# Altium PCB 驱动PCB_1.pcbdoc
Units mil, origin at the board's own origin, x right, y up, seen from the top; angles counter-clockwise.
Board outline 1915 x 3750 mil, 2 copper layers (Top Layer, Bottom Layer); 35 components, 43 nets, 159 pads, 130 vias.
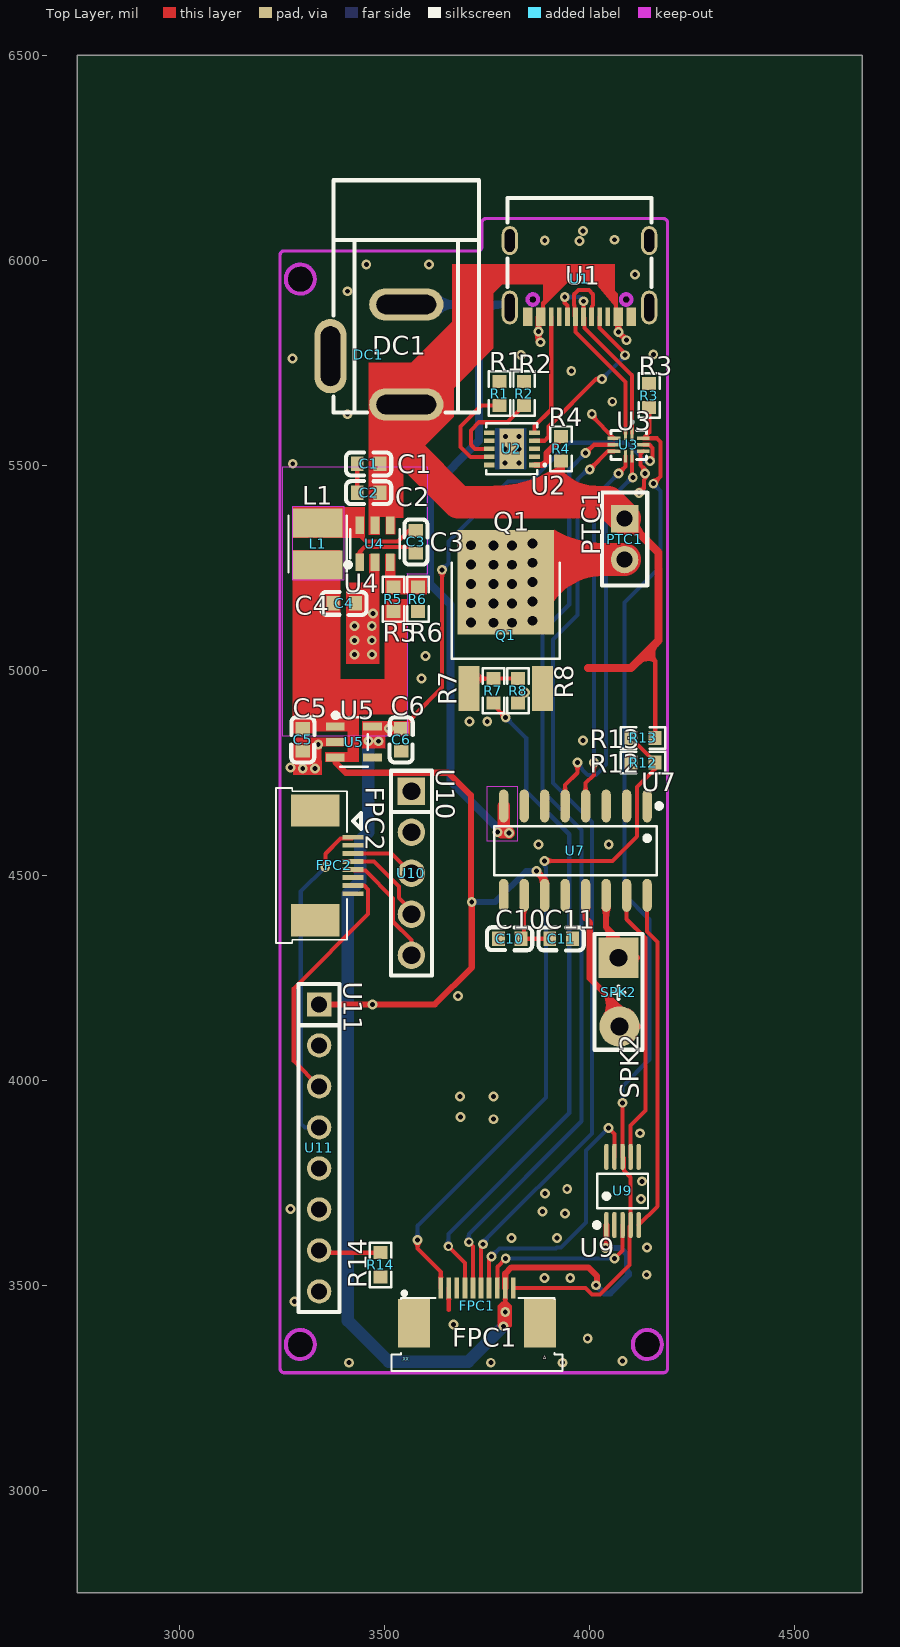
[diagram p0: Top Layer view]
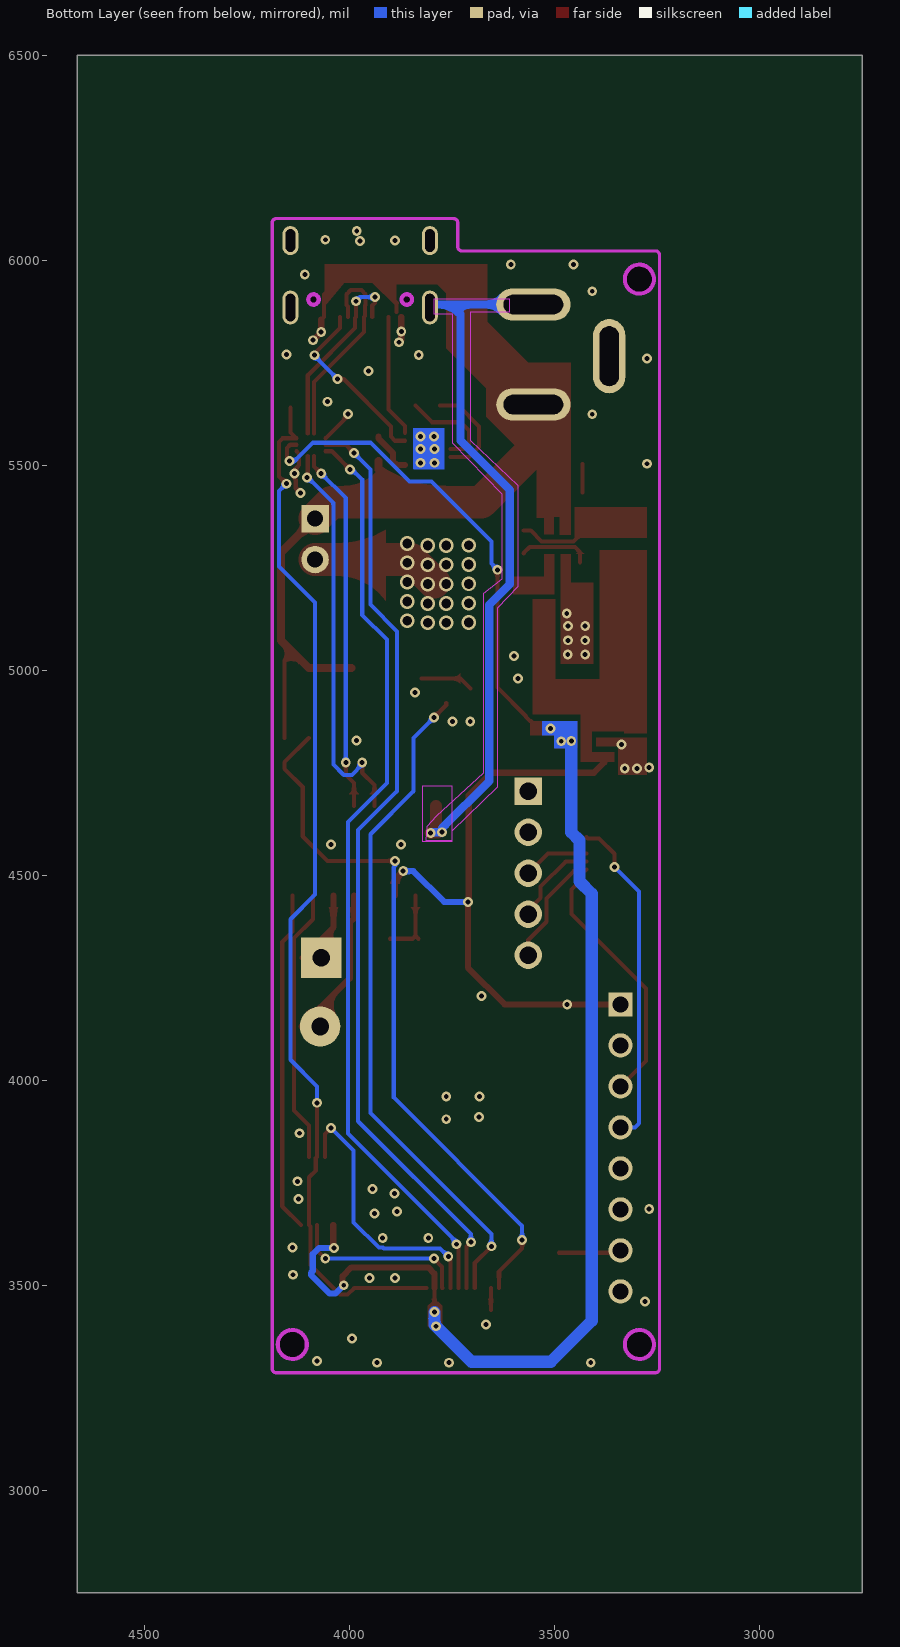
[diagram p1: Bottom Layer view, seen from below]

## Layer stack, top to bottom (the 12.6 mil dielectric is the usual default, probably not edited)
Top Layer: signal copper (thickness not stored)
Dielectric: dielectric 12.6, FR-4, Dk 4.8
Bottom Layer: signal copper (thickness not stored)

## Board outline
4665,2750 2750,2750 2750,6500 4665,6500
cut-out: 3329.43,5953.89 ccw(c3294,5953.67) 3258.57,5953.89 ccw(c3294,5954.11)
cut-out: 3329.43,3355.47 ccw(c3294,3355.25) 3258.57,3355.47 ccw(c3294,3355.69)
cut-out: 4175.89,3355.47 ccw(c4140.45,3355.47) 4105.02,3355.47 ccw(c4140.45,3355.47)

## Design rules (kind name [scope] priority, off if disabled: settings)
BoardOutlineClearance copperThickness1oz [All] p0: genericclearance=10 ignorepadtopadclearanceinfootprint=FALSE except(0: Arc-SplitContinuation Track-SplitContinuation SMDPad-SplitContinuation THPad-SplitContinuation Via-SplitContinuation Fill-SplitContinuation Poly-SplitContinuation Region-SplitContinuation Text-SplitContinuation; 6: Track-CutoutEdge SMDPad-CutoutEdge THPad-CutoutEdge Via-CutoutEdge Region-CutoutEdge; 11.8: Track-OutlineEdge SMDPad-OutlineEdge THPad-OutlineEdge Via-OutlineEdge Fill-OutlineEdge Region-OutlineEdge Poly-OutlineEdge Text-OutlineEdge Fill-CutoutEdge)
BoardOutlineClearance copperThickness2oz [All] p0: genericclearance=10 ignorepadtopadclearanceinfootprint=FALSE except(0: Arc-SplitContinuation Track-SplitContinuation SMDPad-SplitContinuation THPad-SplitContinuation Via-SplitContinuation Fill-SplitContinuation Poly-SplitContinuation Region-SplitContinuation Text-SplitContinuation; 6: Track-CutoutEdge SMDPad-CutoutEdge THPad-CutoutEdge Via-CutoutEdge Region-CutoutEdge; 11.8: Track-OutlineEdge SMDPad-OutlineEdge THPad-OutlineEdge Via-OutlineEdge Fill-OutlineEdge Region-OutlineEdge Poly-OutlineEdge Text-OutlineEdge Fill-CutoutEdge)
Clearance copperThickness1oz [(InNet('GND') OR InNet('3V3') OR InNet('ADC_VIN') OR InNet('$2N1457') OR InNet('$2N1458') OR InNet('VIN') OR InNet('5V') OR InNet('$2N1719') OR InNet('ESP_TX') OR InNet('ESP_RX') OR InNet('DN1') OR InNet('DP1') OR InNet('$2N173') OR InNet('$2N169') OR InNet('$2N860') OR InNet('$2N846') OR InNet('$2N1461') OR InNet('$2N861') OR InNet('DAC') OR InNet('SPK2') OR InNet('SPK1') OR InNet('SCK') OR InNet('DOUT') OR InNet('CC1') OR InNet('DN') OR InNet('DP') OR InNet('CC2') OR InNet('USBDM') OR InNet('USBDP') OR InNet('CH7800_RX') OR InNet('CH7800_TX') OR InNet('SW') OR InNet('PTC') OR InNet('$2N3080') OR InNet('GPIO17') OR InNet('GPIO16') OR InNet('GPIO15') OR InNet('SCL') OR InNet('SDA') OR InNet('AD0') OR InNet('XDA') OR InNet('XCL') OR InNet('INT'))] p1: gap=7 ignorepadtopadclearanceinfootprint=FALSE except(4: Track-Track; 6: Track-SMDPad SMDPad-SMDPad Track-THPad SMDPad-THPad THPad-THPad Track-Via SMDPad-Via THPad-Via Via-Via SMDPad-Fill THPad-Fill Via-Fill Fill-Fill Track-Region SMDPad-Region THPad-Region Via-Region Region-Region Track-Poly SMDPad-Poly THPad-Poly Via-Poly Fill-Poly Region-Poly Poly-Poly Track-Text SMDPad-Text THPad-Text Via-Text Fill-Text Region-Text Poly-Text Text-Text; 6.9: Track-Hole SMDPad-Hole THPad-Hole Via-Hole Fill-Hole Region-Hole Poly-Hole Text-Hole Sheet-Hole; 11.8: Track-Fill Fill-Region Track-Sheet SMDPad-Sheet THPad-Sheet Via-Sheet Fill-Sheet Region-Sheet Poly-Sheet Text-Sheet)
Clearance copperThickness2oz [All] p1: gap=7 ignorepadtopadclearanceinfootprint=FALSE except(6: Track-SMDPad SMDPad-SMDPad Track-THPad SMDPad-THPad THPad-THPad Track-Via SMDPad-Via THPad-Via Via-Via SMDPad-Fill THPad-Fill Via-Fill Fill-Fill Track-Region SMDPad-Region THPad-Region Via-Region Region-Region Track-Poly SMDPad-Poly THPad-Poly Via-Poly Fill-Poly Region-Poly Poly-Poly Track-Text SMDPad-Text THPad-Text Via-Text Fill-Text Region-Text Poly-Text Text-Text; 6.9: Track-Hole SMDPad-Hole THPad-Hole Via-Hole Fill-Hole Region-Hole Poly-Hole Text-Hole Sheet-Hole; 8: Track-Track; 11.8: Track-Fill Fill-Region Track-Sheet SMDPad-Sheet THPad-Sheet Via-Sheet Fill-Sheet Region-Sheet Poly-Sheet Text-Sheet)
DiffPairsRouting differentialPair [All] p1: maxuncoupledlength=10 minlimit=6 maxlimit=6 mostfreqgap=6 toplayer_minwidth=5 toplayer_prefwidth=10 toplayer_maxwidth=100 bottomlayer_minwidth=5 bottomlayer_prefwidth=10 bottomlayer_maxwidth=100
PasteMaskExpansion pasteMaskExpansion [All] p1: expansion=0
PlaneConnect innerPlane [All] p1: planeconnectstyle=Relief reliefexpansion=20 reliefentries=4 reliefconductorwidth=10 reliefairgap=10
PolygonConnect copperRegion [All] p1: connectstyle=Relief reliefentries=4 reliefconductorwidth=10 polygonreliefangle="90 Angle" airgapwidth=10
RoutingVias viaSize [All] p1: viastyle="Through Hole" holewidth=12.0078 minholewidth=11.811 maxholewidth=248.0314 width=24.0158 minwidth=19.685 maxwidth=393.7008
SolderMaskExpansion solderMaskExpansion [All] p1: useseparateexpansions=TRUE expansion=2 expansionbottom=2
Width copperThickness1oz [All] p1: maxlimit=100 minlimit=5 preferedwidth=10
Width copperThickness2oz [All] p1: maxlimit=100 minlimit=8 preferedwidth=10

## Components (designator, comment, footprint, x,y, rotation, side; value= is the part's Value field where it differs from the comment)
C1 "CGA0603X7R104K500JT" C0603 3460.47,5503.23 r180 top
C2 "CL10A106KP8NNNC" C0603 3460.47,5433.23 r180 top
C3 "CGA0603X7R104K500JT" C0603 3576.08,5313.01 r90 top
C4 "CGA0603X7R104K500JT" C0603 3401.08,5163.01 r0 top
C5 "CGA0603X7R104K500JT" C0603 3300,4830 r270 top
C6 "CL10A106KP8NNNC" C0603 3540,4830 r270 top
C10 "CL10A105KA8NNNC" C0603 3805,4345 r0 top
C11 "CL10A105KA8NNNC" C0603 3930,4345 r180 top
DC1 "DC005" DC-IN-TH_DC005 3460,5770 r270 top locked
FPC1 "F0501-T-10-20T-R" FPC-SMD_F0501-T-10-20T-R 3725,3450 r0 top
FPC2 "F0501-T-08-20T-R" FPC-SMD_8P-P0.50_L4.4-W9.6 3376.34,4523.81 r270 top
L1 "CD32-4R7M 4.7UH" IND-SMD_L3.5-W3.0 3336.08,5308.01 r90 top
PTC1 "HDR-F_2.54_1x2P" HDR-TH_2P-P2.54-V-F 4085,5320 r270 top
Q1 "AOD4184L" TO-252-2_L6.6-W6.1-P4.57-LS9.9-TL-CW 3795,5085 r90 top
R1 "0603WAF1002T5E" R0603 3780,5675 r90 top
R2 "0603WAF1002T5E" R0603 3840,5675 r90 top
R3 "0603WAF1002T5E" R0603 4145,5670 r270 top
R4 "0603WAF100JT5E" R0603 3930,5540 r270 top
R5 "FRC0603F2703TS" R0603 3521.08,5173.01 r270 top
R6 "0603WAF5102T5E" R0603 3581.08,5173.01 r90 top
R7 "0603WAF1000T5E" R0603 3765,4950 r90 top
R8 "0603WAF1002T5E" R0603 3825,4950 r270 top
R12 "0603WAF5102T5E" R0603 4130,4775 r180 top
R13 "0603WAF2703T5E" R0603 4130,4835 r180 top
R14 "Res_0603" R0603 3489.66,3549.66 r90 top
SPK2 "GSPK3013P-8R0.15W" SPK-TH_BD30.0-P15.00-D0.8-L-RD 4070,4215 r270 top
U1 "TYPE-C16PIN" USB-C-SMD_TYPE-C16PIN 3975,5955 r180 top
U2 "HUSB238_002DD" DFN-10_L3.0-W3.0-P0.50-BL-EP2.5 3810,5540 r90 top
U3 "BL1532TQFN" QFN-10_L1.4-W1.8-P0.40-BL 4095,5550 r180 top
U4 "RY8411_C2935411" SOT-23-6_L2.9-W1.6-P0.95-LS2.8-TL 3476.14,5308.63 r90 top
U5 "ME6212C33M5G" SOT-23-5_L3.0-W1.7-P0.95-LS2.8-BL 3425,4825 r270 top
U7 "CH7800" SOP-16_L9.9-W3.9-P1.27-LS6.0-BL 3965,4560 r180 top
U9 "BL1555MM" MSOP-10_L3.0-W3.0-P0.50-LS5.0-BL 4080,3730 r0 top
U10 "HB-PH3-25415PB2GOP" HDR-TH_5P-P2.54-V-M 3565,4505 r270 top
U11 "HB-PH3-25418PB2GOP" HDR-TH_8P-P2.54-V-M 3340,3835 r270 top

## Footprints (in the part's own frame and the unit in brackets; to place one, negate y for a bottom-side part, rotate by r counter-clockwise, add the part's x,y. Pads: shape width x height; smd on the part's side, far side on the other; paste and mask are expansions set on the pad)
C0603 [mm]
  rect 0.8x0.9 smd: 1(-0.7,0) 2(0.7,0)
  silkscreen extent -1.41,-0.71 1.39,0.72
DC-IN-TH_DC005 [mm]
  oval 2x4.6 hole 1.2 slot 3.7 at 90 deg: 1(3.1,2.35) 2(-3.1,2.35)
  oval 4.6x2 hole 1.2 slot 3.7 at 0 deg: 3(0.1,-2.35)
  silkscreen extent -10.8,-2.15 3.6,6.85
DFN-10_L3.0-W3.0-P0.50-BL-EP2.5 [mm]
  rect 0.28x0.665 smd: 1(-1,-1.407) 2(-0.5,-1.407) 3(0,-1.407) 4(0.5,-1.407) 5(1,-1.407) 6(1,1.407) 7(0.5,1.407) 8(0,1.407) 9(-0.5,1.407) 10(-1,1.407)
  rect 2.5x1.5 smd: 11(0,0)
  silkscreen extent -1.58,-2.12 1.58,1.58
FPC-SMD_8P-P0.50_L4.4-W9.6 [mm]
  rect 2x3 smd: 0(-3.4,-1.175) 0(3.4,-1.175)
  rect 0.3x1.3 smd: 1(-1.75,1.175) 2(-1.25,1.175) 3(-0.75,1.175) 4(-0.25,1.175) 5(0.25,1.175) 6(0.75,1.175) 7(1.25,1.175) 8(1.75,1.175)
  silkscreen extent -4.8,-3.6 4.8,1.68
FPC-SMD_F0501-T-10-20T-R [mm]
  rect 0.3x1.3 smd: 1(-2.25,1.097) 2(-1.75,1.097) 3(-1.25,1.097) 4(-0.75,1.097) 5(-0.25,1.097) 6(0.25,1.097) 7(0.75,1.097) 8(1.25,1.097) 9(1.75,1.097) 10(2.25,1.097)
  rect 2x3 smd: 11(3.9,-1.097) 12(-3.9,-1.097)
  silkscreen extent -5.3,-4.03 5.3,0.87
HDR-TH_2P-P2.54-V-F [mm]
  rect 1.7x1.7 hole 1: 1(-1.27,0)
  round 1.7 hole 1: 2(1.27,0)
  silkscreen extent -2.88,-1.39 2.88,1.4
HDR-TH_5P-P2.54-V-M [mm]
  rect 1.7x1.7 hole 1.1: 1(-5.08,0)
  round 1.7 hole 1.1: 2(-2.54,0) 3(0,0) 4(2.54,0) 5(5.08,0)
  silkscreen extent -6.35,-1.27 6.35,1.27
HDR-TH_8P-P2.54-V-M [mm]
  rect 1.5x1.5 hole 1: 1(-8.89,0)
  round 1.5 hole 1: 2(-6.35,0) 3(-3.81,0) 4(-1.27,0) 5(1.27,0) 6(3.81,0) 7(6.35,0) 8(8.89,0)
  silkscreen extent -10.16,-1.27 10.16,1.27
IND-SMD_L3.5-W3.0 [mm]
  rect 1.8x3.12 smd: 1(1.303,0) 2(-1.303,0)
  silkscreen extent -1.75,-1.8 1.75,1.8
MSOP-10_L3.0-W3.0-P0.50-LS5.0-BL [mm]
  oval 0.28x1.62 smd: 1(-1,-2.11) 2(-0.5,-2.11) 3(0,-2.11) 4(0.5,-2.11) 5(1,-2.11) 6(1,2.11) 7(0.5,2.11) 8(0,2.11) 9(-0.5,2.11) 10(-1,2.11)
  silkscreen extent -1.74,-2.26 1.58,1.07
QFN-10_L1.4-W1.8-P0.40-BL [mm]
  rect 0.2x0.9 smd: 1(-0.2,-0.65)
  rect 0.2x0.8 smd: 2(0.2,-0.7) 6(0.2,0.7) 7(-0.2,0.7)
  rect 0.8x0.2 smd: 3(0.9,-0.4) 4(0.9,0) 5(0.9,0.4) 8(-0.9,0.4) 9(-0.9,0) 10(-0.9,-0.4)
  silkscreen extent -1.1,-1.48 1.09,0.91
R0603 [mil]
  rect 31.75x34.02 smd: 1(-29.66,0) 2(29.66,0)
  silkscreen extent -55,-26 55,26
SOP-16_L9.9-W3.9-P1.27-LS6.0-BL [mil]
  oval 22.6x80.24 smd: 1(-175,-109.02) 2(-125,-109.02) 3(-75,-109.02) 4(-25,-109.02) 5(25,-109.02) 6(75,-109.02) 7(125,-109.02) 8(175,-109.02) 9(175,109.02) 10(125,109.02) 11(75,109.02) 12(25,109.02) 13(-25,109.02) 14(-75,109.02) 15(-125,109.02) 16(-175,109.02)
  silkscreen extent -210,-115 198,60
SOT-23-5_L3.0-W1.7-P0.95-LS2.8-BL [mm]
  rect 0.49x1.157 smd: 1(-0.95,-1.154) 2(0,-1.154) 3(0.95,-1.154)
  rect 0.49x1.175 smd: 4(0.95,1.154) 5(-0.95,1.154)
  silkscreen extent -1.8,-1.29 1.53,0.85
SOT-23-6_L2.9-W1.6-P0.95-LS2.8-TL [mil]
  rect 42.2x20.95 smd: 1(-45.24,37.4) 2(-45.24,0) 3(-45.24,-37.4) 4(45.24,-37.4) 5(45.24,0) 6(45.24,37.4)
  silkscreen extent -57,-61 35,72
SPK-TH_BD30.0-P15.00-D0.8-L-RD [mm]
  rect 2.5x2.5 hole 1.1: 1(-2.128,0)
  round 2.5 hole 1.1: 2(2.128,0.064)
  silkscreen extent -3.59,-1.47 3.57,1.5
TO-252-2_L6.6-W6.1-P4.57-LS9.9-TL-CW [mm]
  rect 2.8x1.3 smd: 1(-3.292,2.273) 3(-3.292,-2.273)
  rect 6.5x6 smd: 2(3.292,0)
  silkscreen extent -1.46,-3.35 4.51,3.34
USB-C-SMD_TYPE-C16PIN [mm]
  oval 1x2.1 hole 0.6 slot 1.7 at 90 deg: 1(-4.32,1.787) 2(4.32,1.787)
  oval 1x1.8 hole 0.6 slot 1.4 at 90 deg: 3(-4.32,-2.362) 4(4.32,-2.362)
  rect 0.6x1.15 smd: A1B12(-3.2,2.362) A4B9(-2.4,2.362) B1A12(3.2,2.362) B4A9(2.4,2.362)
  rect 0.3x1.15 smd: A5(-1.25,2.362) A6(-0.25,2.362) A7(0.25,2.362) A8(1.25,2.362) B5(1.75,2.362) B6(0.75,2.362) B7(-0.75,2.362) B8(-1.75,2.362)
  Board Outline Layer circle w0.005: c2.89,1.288 r0.325
  Board Outline Layer circle w0.005: c-2.89,1.288 r0.325
  Board Outline Layer circle w0.254: c2.89,1.288 r0.325
  Board Outline Layer circle w0.254: c-2.89,1.288 r0.325
  Multi-Layer board cut-out: 2.565,1.288 2.611,1.128 2.729,1.012 2.89,0.969 3.051,1.012 3.169,1.128 3.215,1.288 3.215,1.288 3.169,1.448 3.051,1.564 2.89,1.607 2.729,1.564 2.611,1.448 2.565,1.288
  Multi-Layer board cut-out: -3.215,1.288 -3.183,1.147 -3.093,1.034 -2.962,0.971 -2.818,0.971 -2.687,1.034 -2.597,1.147 -2.565,1.288 -2.565,1.288 -2.597,1.429 -2.687,1.542 -2.818,1.605 -2.962,1.605 -3.093,1.542 -3.183,1.429 -3.215,1.288
  silkscreen extent -4.45,-5 4.45,0.52

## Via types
v1: diameter 24.02, hole 12.01, Top Layer to Bottom Layer, 110 vias
v2: diameter 36, hole 24, Top Layer to Bottom Layer, 20 vias

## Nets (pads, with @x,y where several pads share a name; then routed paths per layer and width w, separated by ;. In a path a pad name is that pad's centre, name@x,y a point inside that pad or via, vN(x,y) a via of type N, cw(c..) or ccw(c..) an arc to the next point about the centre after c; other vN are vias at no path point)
3V3: C6.1 FPC1.9 U3.9 U5.5 U9.1 | length 3735.6
  Top Layer w10: C6.1 3558.64,4876.2 3560.45,4876.2 3570.3,4886.05 3570.3,4887.86 3640,4957.56 v1(3640,5245) ; v1(3793.89,3434.35) FPC1.9 ; U3.9 4145.49,5550 4153.22,5542.27 4153.22,5516.21 v1(4147.01,5510)
  Top Layer w15: FPC1.9 3793.89,3528.48 3808.89,3543.48 3996.52,3543.48 4017.91,3522.09 4017.91,3502.91 v1(4015,3500) ; v1(4038.76,3591.24) 4040.63,3593.11 U9.1
  Bottom Layer w10: v1(3640,5245) 3655,5260 3655,5314.4 3800.6,5460 3855,5460 3950,5555 4090,5555 4135,5510 v1(4147.01,5510)
  Bottom Layer w15: v1(4015,3500) 4035,3480 4050,3480 4095,3525 4095,3530 4090.49,3534.51 4090.49,3575.9 4075.56,3590.83 4039.17,3590.83 v1(4038.76,3591.24)
  Bottom Layer w30: v1(3460,4827.56) 3460,4605 3440,4585 3440,4485 3410,4455 3410,3413.39 3510,3313.39 3703.39,3313.39 v1(3790,3400) 3793.89,3403.89 v1(3793.89,3434.35)
  other v1: 3484.55,4826.86 3510.37,4858.32
5V: C4.1 C5.1 L1.2 R5.2 U5.1 U5.3 U7.11 U11.1 | length 1461.6
  Top Layer w15: U11.1 v1(3470,4185) 3622.16,4185 3712.14,4274.98 v1(3712.14,4435) ; U5.3 3379.58,4775.42 3405,4750 3655,4750 3710,4695 v1@3710,4435 ; v1(3870,4510) 3890,4490 U7.11
  Bottom Layer w15: v1(3712.14,4435) 3770,4435 3845,4510 v1(3870,4510)
$2N169: Q1.1 R7.2 R8.1 | length 129.5
  Top Layer w10: Q1.1 3729.78,4979.66 R7.2 R8.1
$2N173: PTC1.2 Q1.2 | length 312.9
  Top Layer w80: Q1.2 3850.39,5270 PTC1.2
  other v2: 3710,5116.42 3765,5115.71 3810,5115.71 3860,5120.71 3765,5162.85 3810,5162.85 3710,5163.56 3860,5167.85 3765,5210 3810,5210 3710,5210.71 3860,5215 3765,5257.15 3810,5257.15 3710,5257.85 3860,5262.15 3765,5304.29 3810,5304.29 3710,5305 3860,5309.29
$2N846: R4.1 U2.1 | length 107.6
  Top Layer w15: U2.1 3885.63,5500.63 3895,5510 3895,5530.22 3930,5565.22 R4.1
$2N860: R1.1 U2.9 | length 245.7
  Top Layer w10: U2.9 3709.68,5520.32 3685,5545 3685,5595 3735.34,5645.34 R1.1
$2N861: R2.1 U2.8 | length 238.7
  Top Layer w10: U2.8 3720,5540 3710,5550 3710,5585 3730,5605 3799.66,5605 R2.1
$2N1457: C3.2 L1.1 U4.6 | length 178.9
  Top Layer w10: U4.6 3444.36,5348.26 3444.36,5324.02 3454.2,5314.17 3532.39,5314.17 3558.79,5340.57 C3.2
$2N1458: C3.1 U4.1 | length 173
  Top Layer w10: U4.1 3438.74,5287.82 3451.08,5300.15 3561.38,5300.15 C3.1
$2N1461: R5.1 R6.2 U4.3
$2N1719: C10.2 C11.2 U7.10 | length 174.6
  Top Layer w10: C10.2 C10.2@3840,4352.44 ; U7.10 C10.2@3840,4352.44 ; C11.2 3847.44,4345 C10.2@3840,4352.44
$2N3080: FPC1.3
AD0: R14.2 U11.7 | length 152
  Top Layer w10: U11.7 3345.68,3579.32 R14.2
ADC_VIN: FPC1.1 R12.1 R13.2 | length 1729
  Top Layer w10: v1(3580,3610) 3580,3590 3636.41,3533.59 FPC1.1 ; v1(3890,4535) 4055,4535 4115,4595 4115,4715 4159.66,4759.66 R12.1 4159.66,4775.68 R13.2
  Bottom Layer w10: v1(3580,3610) 3580,3645 3892.99,3957.99 3892.99,4519.52 3890,4522.52 v1(3890,4535)
CC1: U1.A5 U2.4 | length 442.7
  Top Layer w10: U2.4 3890,5559.69 3900,5569.69 3900,5595 4015,5710 v1(4030,5710) ; U1.A5@4024.21,5861.88 4024.21,5834.56 4086.38,5772.39 v1(4086.38,5768.47)
  Bottom Layer w10: v1(4030,5710) 4086.38,5766.38 v1(4086.38,5768.47)
CC2: U1.B5 U2.5 | length 299.4
  Top Layer w10: U2.5 3865.41,5595.41 3906.1,5636.1 U1.B5@3906.1,5861.88
CH7800_RX: U7.16 U9.5 | length 833.3
  Top Layer w10: U9.5 4165,3692.56 4165,4337.56 4140,4362.56 U7.16
CH7800_TX: U7.15 U9.7 | length 672
  Top Layer w10: U7.15 4090,4392.73 4136.02,4346.71 4136.02,3926.02 4099.69,3889.69 U9.7
DAC: U7.9
DN: U1.A7 U1.B7 U3.2 | length 502.2
  Top Layer w10: U1.B7@4004.53,5861.88 4005,5862.35 4005,5887.48 4007.99,5890.48 4007.99,5917.01 3997.93,5927.07 3972.07,5927.07 3962.01,5917.01 3962.01,5890.48 3962.93,5889.56 3962.93,5864.11 3965.16,5861.88 3965.16,5824.84 4087.13,5702.87 U3.2
DN1: FPC1.5 U3.4 | length 2315.6
  Top Layer w10: v1(3705,3605) 3715.16,3594.84 FPC1.5 ; v1(3990,5530) 4010,5550 U3.4
  Bottom Layer w10: v1(3705,3605) 3705,3625 3980,3900 3980,4610 3885,4705 3885,5095 3950,5160 3950,5490 v1(3990,5530)
DOUT: U9.10
DP: U1.A6 U1.B6 U3.1 | length 472.3
  Top Layer w10: v1(3939.02,5910) 3939.02,5895.98 3945.47,5889.53 U1.B6@3945.47,5861.88 ; v1(3985,5900) 3985,5862.04 3984.84,5861.88 3987.64,5859.08 3987.64,5834.69 4102.87,5719.46 U3.1@4102.87,5577.56
  Bottom Layer w10: v1(3939.02,5910) 3975,5910 v1(3985,5900)
DP1: FPC1.6 U3.5 | length 2266.2
  Top Layer w10: FPC1.6 3734.84,3594.84 v1(3740,3600) ; v1(4000,5490) 4044.25,5534.25 U3.5
  Bottom Layer w10: v1(3740,3600) 3740,3605 4005,3870 4005,4630 3910,4725 3910,5075 3970,5135 3970,5465 3995,5490 v1(4000,5490)
ESP_RX: FPC1.7 U9.9 | length 673.8
  Top Layer w10: FPC1.7 3754.53,3564.53 v1(3760,3570) ; v1(4046.01,3883.5) 4060.32,3869.19 U9.9
  Bottom Layer w10: v1(3760,3570) 3780,3590 3917.48,3590 3919.49,3592.01 3929.52,3592.01 3990.77,3653.25 3990.77,3828.25 v1(4046.01,3883.5)
ESP_TX: FPC1.8 U9.3 | length 435.6
  Top Layer w10: FPC1.8 3775,3493.96 3775,3545 v1(3795,3565) ; v1(4060,3565) 4080,3585 U9.3
  Bottom Layer w10: v1(3795,3565) v1(4060,3565)
GND: C1.2 C2.2 C4.2 C5.2 C6.2 C10.1 C11.1 DC1.2 DC1.3 FPC1.2 FPC1.11 FPC1.12 FPC2.0 Q1.3 R1.2 R2.2 R3.1 R6.1 R8.2 R12.2 R14.1 U2.11 U3.3 U3.8 U4.2 U5.2 U7.8 U7.12 U9.6 U11.2 | length 2104.5
  Top Layer w10: C2.2 C1.2 ; 3656.11,3440 FPC1.2 ; v1(4005,5625) 4005,5620.32 U3.3@4059.57,5565.75 ; v1(4120.18,5432.75) 4132.01,5444.58 4132.01,5464.52 4135,5467.52 v1(4135,5480) 4135,5489.49 4124.02,5500.48 4124.02,5527.84 U3.8
  Top Layer w30: U7.8 3790,4610 3785,4605 3800.97,4605 v1(3802.99,4602.98)
  Bottom Layer w20: DC1.2 3753.47,5892.04 ; v1(3802.99,4602.98) 3800.97,4605 v1(3775,4605) 3775,4615 3660,4730 3660,5160 3610,5210 3610,5440 3730,5560 3730,5868.57 3753.47,5892.04 ; 3804.72,5882.75 3795.43,5892.04 3753.47,5892.04
  other v1: 3412.64,3311.09 3758.66,3311.09 3933.66,3311.09 4080,3315 3995,3370 3667.76,3403.86 3280,3460 3890,3517.99 3952.34,3517.99 4138.89,3525.68 4140,3592 3808.8,3615 3920,3615 3940,3675 3885,3680 3270,3686.12 4125,3710 3891.26,3723.74 3945,3735 4127.67,3753.54 4122.68,3870.65 3765,3905 3685,3910 3683.69,3960 3765,3960 3678.89,4205.68 3875,4575 4046.38,4575 3299.99,4760.61 3329.71,4760.61 3270,4762.71 3337.81,4818.97 3983.68,4828.29 3706.46,4875 3750,4875 3841.65,4945.79 3590,4980 3599.79,5034.75 3426.08,5038.01 3468.75,5038.01 3426.08,5073.01 3468.4,5073.01 3426.15,5107.65 3468.4,5107.65 3471.08,5138.01 3275.62,5503.64 3793.33,5506.01 3827.51,5506.01 3793.33,5540 3827.51,5540 3795,5570 3827.51,5570 3408.89,5624.44 4055,5655 3955,5730 3275,5760 3832.08,5769.09 4155,5770 3408.89,5924.44 4110,5965 3455,5990 3607.59,5990 3975,6047.11 3890.29,6048.12 4060,6050 3983.37,6071.38
GPIO15: FPC2.3 U10.3 | length 162.4
  Top Layer w10: FPC2.3 3516.66,4553.34 U10.3
GPIO16: FPC2.4 U10.4 | length 217.4
  Top Layer w10: FPC2.4 3473.48,4533.66 3535,4472.14 3535,4445 3565,4415 U10.4
GPIO17: FPC2.5 U10.5 | length 284
  Top Layer w10: FPC2.5 3425.4,4511.18 3452.75,4511.18 3520.55,4443.37 3520.55,4386.59 3565,4342.14 U10.5
INT: U11.8
PTC: FPC1.4 R7.1 | length 1642.7
  Top Layer w10: v1(3655,3595) 3695.47,3554.53 FPC1.4 ; R7.1 3765,4915 v1(3795,4885)
  Bottom Layer w10: v1(3655,3595) 3655,3625 3950,3920 3950,4600 3845,4705 3845,4835 v1(3795,4885)
SCK: U9.2
SCL: FPC2.7 U11.3 | length 621.4
  Top Layer w10: U11.3 3278.11,4046.89 3278.11,4224.02 3459.18,4405.09 3459.18,4465.37 3449.96,4474.6 FPC2.7
SDA: FPC2.1 U11.4 | length 815.7
  Top Layer w10: v1(3355,4520) 3355,4552.45 3392.46,4589.92 3419.81,4589.92 FPC2.1
  Bottom Layer w10: U11.4 3305,3885 3295,3895 3295,4460 v1(3355,4520)
SPK1: SPK2.1 U7.14 | length 183.3
  Top Layer w15: U7.14 4040,4373.77 SPK2.1@4115,4298.77
SPK2: SPK2.2 U7.13 | length 372.6
  Top Layer w15: U7.13 3990,4395 4000,4385 4000,4248.72 SPK2.2@4117.5,4131.22
SW: FPC1.10 R3.2 U3.10 U9.4 U9.8 | length 2566.6
  Top Layer w10: FPC1.10 3989.31,3493.18 4005.48,3477.01 4024.52,3477.01 4096.5,3548.98 4096.5,3643.74 U9.4 4099.69,3763.36 4083.19,3779.86 4083.19,3809.88 U9.8 v1(4080,3945) ; R3.2 4145,5580.32 4130.43,5565.75 4164.25,5565.75 4172.86,5557.14 4172.86,5472.86 v1(4155,5455)
  Bottom Layer w10: v1(4080,3945) 4080,3985 4145,4050 4145,4392.73 4085,4452.73 4085,5165 4172.86,5252.86 4172.86,5437.14 v1(4155,5455)
USBDM: U3.6 U7.4 | length 888.6
  Top Layer w10: U7.4 3990,4725 4010,4745 v1@4010,4770 ; v1(4070,5480) 4087.13,5497.13 U3.6
  Bottom Layer w10: v1(4010.05,4775) 4010.05,5420.05 v1(4070,5480)
USBDP: U3.7 U7.5 | length 995.8
  Top Layer w10: U7.5 3940,4720 3970,4750 v1(3970,4775) ; U3.7 4102.87,5472.13 v1(4105,5470)
  Bottom Layer w10: v1(3970,4775) 3970,4770 3995,4745 4015,4745 4040,4770 4040,5405 4040.55,5405.55 4040.55,5408.01 4102.54,5470 v1(4105,5470)
VIN: C1.1 C2.1 DC1.1 PTC1.1 R4.2 R13.1 U4.4 U4.5 | length 1844.1
  Top Layer w10: 3874.61,5861.88 3875.03,5862.3 ; 3885.61,5895.61 3910.06,5920.06 ; 3886.42,5873.69 3886.42,5895 3887.93,5895 ; 4035,5945 4063.58,5916.42 4063.58,5861.88 4070,5855.46 ; 4138.5,5043.5 4159.66,5022.33 R13.1
  Top Layer w15: 3874.61,5861.88 v1(3874.61,5826.35) 3874.61,5805.39 v1(3880,5800) ; 4070,5855.46 v1(4070,5825) v1(4090,5805)
  Top Layer w20: 3875,5435 3930,5490 R4.2 ; 3995.78,5005.4 4100.4,5005.4 4138.5,5043.5 4167.86,5072.86 4167.86,5287.14 PTC1.1
  Top Layer w80: DC1.1 3552.51,5537.48 3680,5410 4045,5410 PTC1.1
XCL: U11.6
XDA: U11.5
pads on no net: FPC2.2 FPC2.6 FPC2.8 U1.1 U1.2 U1.3 U1.4 U1.A1B12 U1.A4B9 U1.A8 U1.B1A12 U1.B4A9 U1.B8 U2.2 U2.3 U2.6 U2.7 U2.10 U5.4 U7.1 U7.2 U7.3 U7.6 U7.7 U10.1 U10.2

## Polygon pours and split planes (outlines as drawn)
GND on Top Layer (solid, remove dead copper, pour order 0): 3025,6190 4415,6190 4415,3000 3025,3000
$2N173 on Bottom Layer (solid, remove dead copper, pour order 4): 3670,5505 3955,5505 cw(c3955,5495) 3965,5495 3965,5044.48 cw(c3955,5044.48) 3955,5034.48 3670,5034.48 cw(c3670,5044.48) 3660,5044.48 3660,5495 cw(c3670,5495)
GND on Bottom Layer (solid, remove dead copper, pour order 6): 3000,6250 4390,6250 4390,3060 3000,3060
VIN on Bottom Layer (solid, remove dead copper, pour order 2): 3854.92,5846.88 4106.89,5846.88 4106.89,5795.48 4100.98,5789.58 3855,5789.58 3854.92,5789.66

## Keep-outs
Top Layer:
  region: 3275,5400 3400,5400 3400,5220 3275,5220
  region: 3250,5495 3250,4840 3555.78,4840 3555.78,5234.22 3555,5235 3605,5235 3605,5495
Bottom Layer:
  region: 3610,5905 3795,5905 3795,5870 3750.88,5870 3750.88,5554.86 3630,5430.96 3630,5221.96 3675,5186.23 3675,4749.16 3790,4643.8 3813.11,4618.11 3815,4585 3750,4585 3750,4608.56 3640,4715.47 3640,5152.17 3589.6,5204.31 3589.6,5449.53 3705,5560 3705,5875 3610,5875
Board Outline Layer:
  circle w1: c3294,5953.89 r35.43
  circle w10: c3294,5953.89 r35.43
  circle w1: c3294,3355.47 r35.43
  circle w10: c3294,3355.47 r35.43
  circle w1: c4140.46,3355.47 r35.43
  circle w10: c4140.46,3355.47 r35.43
  region: 3750,4717.56 3822.99,4717.56 3822.99,4583.08 3750,4583.08
  lines w7.87: 3244.79,3296.58 3244.79,6012.79 cw(c3254.79,6012.79) 3254.79,6022.79 3726.91,6022.79 ccw(c3726.91,6032.79) 3736.91,6032.79 3736.91,6091.53 cw(c3746.91,6091.53) 3746.91,6101.53 4179.67,6101.53 cw(c4179.67,6091.53) 4189.67,6091.53 4189.67,3296.58 cw(c4179.67,3296.58) 4179.67,3286.58 3254.79,3286.58 cw(c3254.79,3296.58) 3244.79,3296.58

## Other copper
Top Layer:
  region net $2N1457: 3276.08,5323.01 3276.08,5398.01 3451.08,5398.01 3451.08,5323.01
  region net $2N1461: 3501.08,5282.61 3526.08,5283.01 3526.08,5228.01 3602.09,5228.01 3602.09,5184.79 3501.08,5184.79
  region net GND: 3486.08,5283.01 3461.84,5283.01 3461.84,5213.01 3406.08,5213.01 3406.08,5015.78 3486.08,5015.78
  region net VIN: 3461.17,5330.98 3461.17,5522.73 3460.78,5522.73 3460.78,5750 3565,5750 3665,5850 3665,5990 4060.98,5990 4060.98,5887.84 4013.78,5945 3945,5945 3890,5890 3886.42,5893.58 3886.42,5941.6 3786.6,5941.6 3765,5920 3765,5785 3667.98,5687.98 3667.98,5617.98 3572.73,5522.73 3544.82,5522.73 3544.82,5372.44 3526.04,5372.44 3525.67,5331.22 3502.75,5331.22 3502.99,5374.9 3488.36,5375 3488.36,5330.98
  region net 5V: 3275.85,4903.09 3276.08,4903.09 3276.08,5293.01 3391.08,5293.01 3391.08,4978.01 3499.71,4978.01 3499.71,5173.01 3553.49,5173.01 3553.49,4893.01 3436.91,4893.01 3436.91,4776.48 3355,4776.48 3355,4800 3409.89,4800 3409.89,4851.42 3330.25,4851.42 3330.25,4845.85 3275.85,4845.85
  region net GND: 3399.05,4835.38 3276.57,4835.31 3276.57,4744.64 3345.75,4744.64 3345,4815 3399.05,4815
  region net 3V3: 3445,4876.2 3445,4810 3500.97,4810 3500.97,4840.97 3560.45,4840.97 3560.45,4876.2
  region net 3V3: 3775,3450 3775,3400 3785,3390 3799.68,3390 3809.68,3400 3809.68,3450 3799.68,3460 3785,3460
  region net VIN: 3592.51,5537.48 3512.51,5537.48 3512.78,5544.14 3513.49,5550.75 3514.53,5557.25 3515.77,5563.59 3518.35,5575.61 3519.45,5581.17 3520.26,5586.37 3520.65,5591.15 3520.65,5593.37 3520.5,5595.47 3520.18,5597.43 3519.68,5599.26 3518.99,5600.94 3518.08,5602.48 3516.95,5603.86 3515.57,5605.07 3513.93,5606.12 3512.02,5606.99 3509.82,5607.68 3507.32,5608.18 3504.49,5608.49 3501.33,5608.59 3603.7,5608.59 3600.54,5608.49 3597.71,5608.18 3595.21,5607.68 3593.01,5606.99 3591.1,5606.12 3589.46,5605.07 3588.08,5603.86 3586.95,5602.48 3586.04,5600.94 3585.35,5599.26 3584.85,5597.43 3584.53,5595.47 3584.38,5593.37 3584.38,5591.15 3584.77,5586.37 3585.58,5581.17 3586.68,5575.61 3589.26,5563.59 3590.5,5557.25 3591.54,5550.75 3592.25,5544.14
  region net ADC_VIN: 3631.41,3533.59 3641.41,3533.59 ccw(c3763.07,3533.59) 3642.32,3518.77 3630.51,3518.77 ccw(c3509.76,3533.59)
  region net GND: 3661.11,3452.59 3651.11,3452.59 ccw(c3526.41,3452.59) 3650.2,3467.59 3662.01,3467.59 ccw(c3785.8,3452.59)
  region net 3V3: 3798.89,3452.59 3788.89,3452.59 ccw(c3664.2,3452.59) 3787.99,3467.59 3799.8,3467.59 ccw(c3923.59,3452.59)
  region net VIN: 4129.07,5340.07 4114.93,5325.93 ccw(c4083.11,5283.5) 4083.11,5336.54 4118.46,5371.89 ccw(c4171.5,5371.89)
  region net $2N173: 4033.11,5310 4033.11,5230 ccw(c4033.11,5080) 3913.11,5170 3913.11,5342.56 ccw(c4033.11,5547.42)
  region net $2N169: 3746.11,4984.66 3746.11,4974.66 ccw(c3746.11,4955.91) 3731.11,4967.16 3731.11,4992.16 ccw(c3746.11,5003.41)
  region net $2N1457: 3449.36,5324.02 3439.36,5324.02 ccw(c3430.5,5324.02) 3431.86,5332.77 3449.22,5332.77 ccw(c3721.11,5332.77)
  region net $2N1458: 3433.74,5287.82 3443.74,5287.82 ccw(c3449.22,5290.66) 3449.22,5284.49 3428.27,5284.49 ccw(c3428.27,5290.66)
  region net USBDM: 3985,4712.84 3995,4712.84 3995.27,4710.08 3995.98,4707.47 3996.99,4705.06 3998.15,4702.9 4000.31,4699.55 4001.03,4698.46 4001.3,4697.84 3978.7,4697.84 3978.97,4698.46 3979.69,4699.55 3981.85,4702.9 3983.01,4705.06 3984.02,4707.47 3984.73,4710.08
  region net USBDP: 3935,4712.84 3945,4712.84 3945.27,4710.08 3945.98,4707.47 3946.99,4705.06 3948.15,4702.9 3950.31,4699.55 3951.03,4698.46 3951.3,4697.84 3928.7,4697.84 3928.97,4698.46 3929.69,4699.55 3931.85,4702.9 3933.01,4705.06 3934.02,4707.47 3934.73,4710.08
  region net SPK1: 4047.5,4399.66 4032.5,4399.66 4032.34,4403.82 4031.91,4407.78 4031.3,4411.46 4030.6,4414.75 4029.29,4419.81 4028.7,4422.16 4051.3,4422.16 4050.71,4419.81 4049.4,4414.75 4048.7,4411.46 4048.09,4407.78 4047.66,4403.82
  region net SPK2: 3997.5,4399.66 3982.5,4399.66 3982.34,4403.82 3981.91,4407.78 3981.3,4411.46 3980.6,4414.75 3979.29,4419.81 3978.7,4422.16 4001.3,4422.16 4000.71,4419.81 3999.4,4414.75 3998.7,4411.46 3998.09,4407.78 3997.66,4403.82
  region net 5V: 3868.24,4501.16 3890.14,4500.46 3892.22,4498.3 3894.24,4495.99 3896.12,4493.55 3897.81,4491 3899.24,4488.33 3900.34,4485.57 3901.05,4482.72 3901.3,4479.8 3878.7,4479.8 3878.47,4482.63 3877.8,4485.52 3876.77,4488.43 3875.43,4491.29 3873.85,4494.05 3872.08,4496.65 3870.19,4499.04
  region net $2N1719: 3845,4407.16 3835,4407.16 3834.73,4409.92 3834.02,4412.53 3833.01,4414.94 3831.85,4417.1 3829.69,4420.45 3828.97,4421.54 3828.7,4422.16 3851.3,4422.16 3851.03,4421.54 3850.31,4420.45 3848.15,4417.1 3846.99,4414.94 3845.98,4412.53 3845.27,4409.92
  region net CC1: 4015,5705 4015,5715 4016.06,5715.09 4017.03,5715.34 4018.78,5716.23 4020.39,5717.5 4021.99,5718.95 4021.99,5701.05 4020.39,5702.5 4018.78,5703.77 4017.03,5704.66 4016.06,5704.91
  region net VIN: 4062.5,5841.41 4077.5,5841.41 4077.41,5839.02 4077.38,5836.88 4077.5,5835.88 4077.77,5834.91 4078.24,5833.95 4078.95,5833.01 4061.05,5833.01 4061.76,5833.95 4062.23,5834.91 4062.5,5835.88 4062.62,5836.88 4062.59,5839.02
  region net 5V: 3886.91,4503.7 3876.3,4493.09 3874.68,4494.85 3873.19,4496.38 3872.39,4497 3871.51,4497.5 3870.51,4497.84 3869.33,4498.01 3881.99,4510.67 3882.16,4509.49 3882.5,4508.49 3883,4507.61 3883.62,4506.81 3885.15,4505.32
  region net USBDP: 3975,4758.59 3965,4758.59 3964.91,4759.71 3964.66,4760.84 3963.77,4763.07 3962.5,4765.17 3961.05,4766.99 3978.95,4766.99 3977.5,4765.17 3976.23,4763.07 3975.34,4760.84 3975.09,4759.71
  region net USBDM: 4015,4758.56 4005,4758.62 4004.91,4759.74 4004.66,4760.88 4003.77,4763.11 4002.51,4765.2 4001.07,4767.03 4018.97,4766.96 4017.51,4765.14 4016.24,4763.04 4015.34,4760.81 4015.09,4759.68
  region net USBDM: 4078.07,5495.14 4085.14,5488.07 4084.41,5487.21 4083.79,5486.24 4082.84,5484.02 4082.26,5481.65 4081.99,5479.33 4069.33,5491.99 4071.65,5492.26 4074.02,5492.84 4076.24,5493.79 4077.21,5494.41
  region net DN1: 3998.07,5545.14 4005.14,5538.07 4004.41,5537.21 4003.79,5536.24 4002.84,5534.02 4002.26,5531.65 4001.99,5529.33 3989.33,5541.99 3991.65,5542.26 3994.02,5542.84 3996.24,5543.79 3997.21,5544.41
  region net DP1: 4008.07,5505.14 4015.14,5498.07 4014.41,5497.21 4013.79,5496.24 4012.84,5494.02 4012.26,5491.65 4011.99,5489.33 3999.33,5501.99 4001.65,5502.26 4004.02,5502.84 4006.24,5503.79 4007.21,5504.41
  region net PTC: 3779.86,4893.07 3786.93,4900.14 3787.79,4899.41 3788.76,4898.79 3790.98,4897.84 3793.35,4897.26 3795.67,4896.99 3783.01,4884.33 3782.74,4886.65 3782.16,4889.02 3781.21,4891.24 3780.59,4892.21
  region net ADC_VIN: 3585,3593.59 3575,3593.59 3574.91,3594.71 3574.66,3595.84 3573.77,3598.07 3572.5,3600.17 3571.05,3601.99 3588.95,3601.99 3587.5,3600.17 3586.23,3598.07 3585.34,3595.84 3585.09,3594.71
  region net ADC_VIN: 3906.41,4540 3906.41,4530 3905.29,4529.91 3904.16,4529.66 3901.93,4528.77 3899.83,4527.5 3898.01,4526.05 3898.01,4543.95 3899.83,4542.5 3901.93,4541.23 3904.16,4540.34 3905.29,4540.09
  region net SW: 4163.07,5470.14 4170.14,5463.07 4169.41,5462.21 4168.79,5461.24 4167.84,5459.02 4167.26,5456.65 4166.99,5454.33 4154.33,5466.99 4156.65,5467.26 4159.02,5467.84 4161.24,5468.79 4162.21,5469.41
  region net 3V3: 3645,5228.59 3635,5228.59 3634.91,5229.71 3634.66,5230.84 3633.77,5233.07 3632.5,5235.17 3631.05,5236.99 3648.95,5236.99 3647.5,5235.17 3646.23,5233.07 3645.34,5230.84 3645.09,5229.71
  region net 3V3: 3788.89,3450.76 3798.89,3450.76 3798.98,3449.64 3799.23,3448.51 3800.13,3446.28 3801.39,3444.19 3802.85,3442.36 3784.94,3442.36 3786.4,3444.19 3787.66,3446.28 3788.56,3448.51 3788.81,3449.64
  region net GND: 4019.32,5613.07 4008.76,5609.48 4007.08,5610.86 4005.16,5611.98 4003.12,5612.89 4001.05,5613.66 4016.71,5622.34 4016.56,5621.24 4016.58,5620.02 4017.05,5617.42 4018,5614.96 4018.62,5613.92
  region net GND: 4128.25,5447.89 4135.32,5440.82 4134.59,5439.96 4133.96,5438.99 4133.02,5436.78 4132.43,5434.4 4132.17,5432.08 4119.51,5444.74 4121.83,5445.01 4124.2,5445.59 4126.41,5446.54 4127.39,5447.16
  region net GND: 4140,5467.52 4130,5467.52 4129.91,5468.47 4129.66,5469.16 4129.27,5469.65 4128.77,5470.04 4127.5,5470.78 4126.79,5471.29 4126.05,5471.99 4143.95,5471.99 4143.21,5471.29 4142.5,5470.78 4141.23,5470.04 4140.73,5469.65 4140.34,5469.16 4140.09,5468.47
  region net GND: 4121.94,5495.48 4132.59,5498.97 4137.26,5494.02 4139.38,5491.95 4142.32,5489.52 4125.01,5486.66 4125.59,5487.84 4125.8,5489 4125.67,5490.13 4125.27,5491.25 4124.65,5492.34 4123.85,5493.41
  region net VIN: 4156.12,5018.8 ccw(c4142.49,4997.08) 4124.36,5015.21 4138.5,5043.5 4166.78,5057.64 ccw(c4184.92,5039.51) 4163.2,5025.87
  region net VIN: 3937.07,5482.93 ccw(c4014.14,5556.66) 4014.14,5450 3890,5410 3765.86,5450 ccw(c3765.86,5735.6) 3922.93,5497.07
  region net SPK1: 4034.7,4368.47 4111.26,4313.12 ccw(c4131.15,4313.12) 4115.23,4301.19 4119.21,4289.26 4039.27,4347.99 ccw(c4020.85,4354.63)
  region net SPK2: 4030.87,4207.24 4075.02,4184.31 4077.31,4182.16 4079.47,4180.43 4081.5,4179.06 4083.43,4177.98 4085.28,4177.15 4087.07,4176.49 4090.56,4175.49 4094.07,4174.51 4095.88,4173.87 4097.76,4173.07 4099.72,4172.03 4101.8,4170.7 4104,4169.02 4106.36,4166.93 4033.25,4160.9 4034.9,4163.36 4036.32,4166.03 4037.49,4168.88 4038.43,4171.86 4039.12,4174.96 4039.58,4178.14 4039.79,4181.37 4039.77,4184.61 4039.5,4187.83 4038.99,4191.01 4038.24,4194.1 4037.25,4197.08 4036.02,4199.92 4034.55,4202.58 4032.83,4205.03
  region net SPK2: 4030.9,4207.21 4075.78,4183.55 4078.08,4181.4 4080.24,4179.68 4082.29,4178.32 4084.24,4177.26 4086.1,4176.44 4087.91,4175.81 4091.44,4174.84 4094.96,4173.88 4096.77,4173.25 4098.65,4172.43 4100.6,4171.38 4102.65,4170.03 4104.82,4168.32 4107.13,4166.18 4033.04,4160.63 4034.7,4163.13 4036.13,4165.82 4037.33,4168.69 4038.29,4171.7 4039.01,4174.81 4039.5,4178 4039.74,4181.23 4039.74,4184.48 4039.5,4187.71 4039.02,4190.89 4038.29,4193.99 4037.31,4196.98 4036.08,4199.83 4034.61,4202.51 4032.88,4204.98
  region net VIN: 3867.11,5813.8 3882.11,5819.87 3882.02,5818.41 3881.81,5817.05 3881.42,5814.62 3881.44,5813.59 3881.75,5812.72 3882.42,5812 3883.58,5811.46 3868.39,5803.05 3868.62,5804.44 3868.61,5805.78 3868.12,5808.38 3867.45,5811 3867.21,5812.37
  region net VIN: 3882.11,5809.94 3867.11,5809.94 3867.2,5812.33 3867.23,5814.47 3867.11,5815.47 3866.84,5816.45 3866.37,5817.4 3865.66,5818.35 3883.56,5818.35 3882.85,5817.4 3882.38,5816.45 3882.11,5815.47 3881.99,5814.47 3882.02,5812.33
Bottom Layer:
  region net 3V3: 3445,4876.2 3445,4810 3501.8,4810 3501.8,4840.97 3530.71,4840.97 3530.71,4876.2
  region net GND: 3770,5590 3770,5490 3844.01,5490 3845.02,5491.01 3845.02,5590
  region net GND: 3664.12,5902.04 3664.12,5882.04 3662.25,5881.95 3660.3,5881.7 3656.2,5880.75 3651.99,5879.27 3647.79,5877.35 3643.76,5875.08 3640.04,5872.55 3636.78,5869.84 3634.12,5867.04 3634.12,5917.04 3636.78,5914.24 3640.04,5911.53 3643.76,5909 3647.79,5906.73 3651.99,5904.81 3656.2,5903.33 3660.3,5902.38 3662.25,5902.13
  region net DP: 3971.46,5906.46 3978.54,5913.54 3979.32,5912.87 3980.12,5912.43 3980.93,5912.17 3981.78,5912.04 3985.67,5911.99 3973.01,5899.33 3972.96,5903.22 3972.83,5904.07 3972.57,5904.88 3972.13,5905.68
  region net DP: 3955.43,5915 3955.43,5905 3954.31,5904.91 3953.17,5904.66 3950.94,5903.77 3948.85,5902.5 3947.02,5901.05 3947.02,5918.95 3948.85,5917.5 3950.94,5916.23 3953.17,5915.34 3954.31,5915.09
  region net CC1: 4080.18,5753.11 4071.55,5758.62 4072.27,5759.48 4072.89,5760.49 4073.82,5762.82 4074.32,5765.31 4074.4,5767.66 4088.52,5756.65 4086.28,5756.17 4084.04,5755.47 4081.96,5754.47
  region net CC1: 4038.07,5725.14 4045.14,5718.07 4044.41,5717.21 4043.79,5716.24 4042.84,5714.02 4042.26,5711.65 4041.99,5709.33 4029.33,5721.99 4031.65,5722.26 4034.02,5722.84 4036.24,5723.79 4037.21,5724.41
  region net 5V: 3853.59,4502.5 3853.59,4517.5 3855.98,4517.41 3858.12,4517.38 3859.12,4517.5 3860.09,4517.77 3861.05,4518.24 3861.99,4518.95 3861.99,4501.05 3861.05,4501.76 3860.09,4502.23 3859.12,4502.5 3858.12,4502.62 3855.98,4502.59
  region net USBDP: 3984.25,4762.82 3973.45,4759.47 3971.79,4760.85 3969.89,4761.99 3967.86,4762.94 3965.83,4763.74 3981.65,4772.11 3981.49,4771.02 3981.5,4769.8 3981.97,4767.19 3982.92,4764.72 3983.55,4763.67
  region net USBDM: 4005.05,4791.41 4015.05,4791.41 4015.13,4790.29 4015.39,4789.16 4016.28,4786.93 4017.55,4784.83 4019,4783.01 4001.1,4783.01 4002.55,4784.83 4003.81,4786.93 4004.71,4789.16 4004.96,4790.29
  region net USBDM: 4061.93,5464.86 4054.86,5471.93 4055.59,5472.79 4056.21,5473.76 4057.16,5475.98 4057.74,5478.35 4058.01,5480.67 4070.67,5468.01 4068.35,5467.74 4065.98,5467.16 4063.76,5466.21 4062.79,5465.59
  region net USBDP: 4094.84,5455.23 4089.61,5464.14 4090.98,5465.91 4091.99,5467.97 4092.71,5470.18 4093.23,5472.4 4103.92,5458.04 4101.58,5458 4099.07,5457.5 4096.72,5456.57 4095.7,5455.95
  region net ESP_RX: 3768.07,3585.14 3775.14,3578.07 3774.41,3577.21 3773.79,3576.24 3772.84,3574.02 3772.26,3571.65 3771.99,3569.33 3759.33,3581.99 3761.65,3582.26 3764.02,3582.84 3766.24,3583.79 3767.21,3584.41
  region net DN1: 3700,3621.41 3710,3621.41 3710.09,3620.29 3710.34,3619.16 3711.23,3616.93 3712.5,3614.83 3713.95,3613.01 3696.05,3613.01 3697.5,3614.83 3698.77,3616.93 3699.66,3619.16 3699.91,3620.29
  region net DP1: 3743.45,3615.53 3754.25,3612.18 3753.55,3611.33 3752.92,3610.28 3751.97,3607.81 3751.5,3605.2 3751.49,3603.98 3751.65,3602.89 3735.83,3611.26 3737.86,3612.06 3739.89,3613.01 3741.79,3614.15
  region net DN1: 3981.93,5514.86 3974.86,5521.93 3975.59,5522.79 3976.21,5523.76 3977.16,5525.98 3977.74,5528.35 3978.01,5530.67 3990.67,5518.01 3988.35,5517.74 3985.98,5517.16 3983.76,5516.21 3982.79,5515.59
  region net DP1: 3987.82,5475.75 3984.47,5486.55 3985.85,5488.21 3986.99,5490.11 3987.94,5492.14 3988.74,5494.17 3997.11,5478.35 3996.02,5478.51 3994.8,5478.5 3992.19,5478.03 3989.72,5477.08 3988.67,5476.45
  region net PTC: 3650,3611.41 3660,3611.41 3660.09,3610.29 3660.34,3609.16 3661.23,3606.93 3662.5,3604.83 3663.95,3603.01 3646.05,3603.01 3647.5,3604.83 3648.77,3606.93 3649.66,3609.16 3649.91,3610.29
  region net PTC: 3810.14,4876.93 3803.07,4869.86 3802.21,4870.59 3801.24,4871.21 3799.02,4872.16 3796.65,4872.74 3794.33,4873.01 3806.99,4885.67 3807.26,4883.35 3807.84,4880.98 3808.79,4878.76 3809.41,4877.79
  region net ADC_VIN: 3575,3626.41 3585,3626.41 3585.09,3625.29 3585.34,3624.16 3586.23,3621.93 3587.5,3619.83 3588.95,3618.01 3571.05,3618.01 3572.5,3619.83 3573.77,3621.93 3574.66,3624.16 3574.91,3625.29
  region net ADC_VIN: 3895,4522.52 3885,4522.52 3884.91,4523.47 3884.66,4524.15 3884.27,4524.65 3883.77,4525.04 3882.5,4525.78 3881.79,4526.29 3881.05,4526.99 3898.95,4526.99 3898.21,4526.29 3897.5,4525.78 3896.23,4525.04 3895.73,4524.65 3895.34,4524.15 3895.09,4523.47
  region net SW: 4170.14,5446.93 4163.07,5439.86 4162.21,5440.59 4161.24,5441.21 4159.02,5442.16 4156.65,5442.74 4154.33,5443.01 4166.99,5455.67 4167.26,5453.35 4167.84,5450.98 4168.79,5448.76 4169.41,5447.79
  region net 3V3: 3648.07,5260.14 3655.14,5253.07 3654.41,5252.21 3653.79,5251.24 3652.84,5249.02 3652.26,5246.65 3651.99,5244.33 3639.33,5256.99 3641.65,5257.26 3644.02,5257.84 3646.24,5258.79 3647.21,5259.41
  region net 3V3: 4125.52,5512.41 4130.11,5521.96 4132.29,5519.86 4133.37,5518.97 4134.46,5518.28 4135.56,5517.86 4136.66,5517.77 4137.78,5518.08 4138.91,5518.87 4139.07,5500.99 4135.64,5503.86 4132.2,5506.6 4128.8,5509.39
  region net 3V3: 3778.89,3412.3 3808.89,3419.51 3808.69,3418.79 3808.13,3418.1 3807.27,3417.42 3806.15,3416.77 3803.42,3415.54 3800.39,3414.41 3797.53,3413.39 3795.3,3412.5 3794.56,3412.1 3794.16,3411.73 3794.14,3411.4 3794.57,3411.11 3778.64,3403.89 3779.21,3406.2 3779.23,3408.02 3779.03,3409.88
  region net GND: 3789.41,4615 3789.41,4595 3786.76,4594.91 3784.26,4594.69 3779.88,4594 3776.66,4593.31 3775,4592.99 3775,4617.01 3776.66,4616.69 3779.88,4616 3784.26,4615.31 3786.76,4615.09
  region net GND: 3758.95,4616.91 3776.13,4628.01 3776.92,4627.11 3777.49,4626.22 3778.13,4624.48 3778.3,4622.79 3778.26,4621.16 3778.27,4619.59 3778.58,4618.09 3778.93,4617.37 3779.46,4616.66 3780.19,4615.97 3781.16,4615.31 3764.22,4610.29 3764.62,4611.5 3764.55,4612.45 3764.09,4613.22 3763.32,4613.89 3761.23,4615.18 3760.07,4615.95
  region net GND: 3786.31,4595 3786.61,4615 3787.73,4614.79 3788.86,4614.25 3791.09,4612.74 3792.16,4612.05 3793.18,4611.6 3794.14,4611.52 3795.01,4611.95 3794.71,4594.28 3793.71,4595.07 3792.77,4595.51 3791.84,4595.67 3790.91,4595.63 3788.84,4595.26
  region net GND: 3722.93,5875.64 ccw(c3709.33,5864.39) 3709.33,5882.04 3753.47,5892.04 3777.61,5882.04 ccw(c3788.71,5809.86) 3737.07,5861.5

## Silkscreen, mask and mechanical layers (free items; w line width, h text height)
Top Solder Mask Layer:
  region: 3865,5035.41 3663.52,5035 3663.52,5286.99 3721.53,5345 3935,5345 3935,5170 3865,5100
Bottom Solder Mask Layer:
  region: 3675,5290 3725,5340 3885,5340 3885,5115 3870,5100 3870,5090 3675,5090
Mechanical Layer:
  circle w1: c3294,5953.89 r35.43
  circle w1: c3294,3355.47 r35.43
  circle w1: c4140.46,3355.47 r35.43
